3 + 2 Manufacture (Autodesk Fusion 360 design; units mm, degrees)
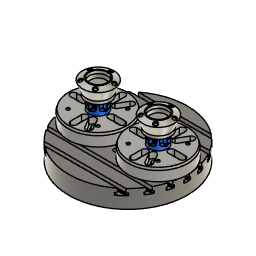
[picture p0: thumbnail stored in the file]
sketch "Sketch1" plane through (0, 0, 0) normal (1, 0, 0) x axis (0, 1, 0)
  line L1 (0, 63.5) -> (0, 0)
  line L2 (42.2596, 63.5) -> (0, 63.5)
  line L3 (66.1278, 54.8127) -> (42.2596, 63.5)
  line L4 (50.8, 12.7) -> (66.1278, 54.8127)
  line L5 (50.8, 0) -> (50.8, 12.7)
  line L6 (0, 0) -> (50.8, 0)
  line L7 (37.6371, 50.8) -> (37.6371, 63.5)
  line L8 (33.0147, 38.1) -> (37.6371, 50.8)
  line L9 (0, 38.1) -> (33.0147, 38.1)
  line L10 (42.2596, 63.5) -> (37.6371, 50.8)
  point P1 (0, 0)
  point P2 (0, 0)
  point P8 (0, 0)
  point P9 (37.6371, 63.5)
  point P12 (0, 38.1)
  point P6 (50.8, 12.7)
  point P7 (50.8, 0)
  point P4 (42.2596, 63.5)
  point P5 (66.1278, 54.8127)
  point P3 (0, 63.5)
  point P10 (37.6371, 50.8)
  coincident P1 P2
  vertical L1
  perpendicular L1 L2
  perpendicular L2 L5
  coincident P1 P8
  horizontal L6
  perpendicular L3 L4
  coincident L2 P9
  perpendicular L2 L7
  coincident L1 P12
  perpendicular L1 L9
  collinear L8 L10
  parallel L4 L10
  dimension "d1" = 101.6
  dimension "d2" distance P6 P7 = 12.7
  dimension "d3" angle L4 L5 = 20
  dimension "d4" distance P4 P5 = 25.4
  dimension "d5" distance P2 P3 = 63.5
  dimension "d7" distance P9 P10 = 12.7
  dimension "d8" distance L2 L9 = 25.4
revolve "Revolve1" sketch "Sketch1" AlongAngle 360 bodies "Part"
work_plane "WorkPlane1" RotateAngle 0
sketch "Sketch2" plane through (0, 54.1937, 59.1563) normal (0, 0.342, 0.9397) x axis (0, 0.9397, -0.342)
  circle C1 centre (0, 0) radius 8.903
  point P1 (0, 0)
  point P2 (0, 0)
  coincident P1 P2
  dimension "d10" diameter C1 = 17.806
copy_paste_bodies "CopyPasteBodies1"
extrude "Extrude1" cut sketch "Sketch2" + "Sketch2" profile of S1:C1 blind -3.175
hole "Hole1" sketch "Sketch2" HoleDepth 12.7 HoleDiameter 10.6426 TipAngle 118
circular_pattern "C-Pattern1" TotalAngle 360
derived_base_feature "Derived Base Feature" bodies "Body1"
base_feature "Base Feature1"
base_feature "Base Feature1" bodies "Body1", "Body2", "Body3", "Body4", "Body5", "Body6"
joint "Assemble2" alignAngle 0 named "d5_2" alignOffsetX 0 named "d6_2" alignOffsetY 0 named "d7_2" alignOffsetZ 0 named "d8_2"
place_component sketch "Sketch2"
sketch "Sketch1" plane through (0, 0, 0) normal (1, 0, 0) x axis (0, 0, -1)
  line L1 (0, 3.1496) -> (0, 0)
  line L2 (-17.1551, 3.1496) -> (0, 3.1496)
  line L3 (-18.9735, 0) -> (-17.1551, 3.1496)
  line L4 (0, 0) -> (-18.9735, 0)
  line L5 (-18.5336, 0) -> (-18.5336, 0.762)
  line L6 (17.1551, 3.1496) -> (0, 3.1496)
  line L7 (18.9735, 0) -> (17.1551, 3.1496)
  line L8 (0, 0) -> (18.9735, 0)
  line L9 (18.5336, 0) -> (18.5336, 0.762)
  line L10 (-44.45, 3.1496) -> (44.45, 3.1496)
  line L11 (-44.45, 34.8996) -> (-44.45, 3.1496)
  line L12 (44.45, 34.8996) -> (-44.45, 34.8996)
  line L13 (44.45, 3.1496) -> (44.45, 34.8996)
  line L14 (-44.45, 34.8996) -> (44.45, 3.1496)
  line L15 (44.45, 34.8996) -> (-44.45, 3.1496)
  circle C1 centre (-19.3548, 1.8796) radius 1.27
  point P1 (0, 0)
  point P2 (0, 0)
  point P6 (0, 0)
  point P8 (-18.5336, 0.762)
  point P9 (-18.5336, 0)
  point P10 (-20.6248, 1.8796)
  point P7 (-19.3548, 1.8796)
  point P3 (0, 3.1496)
  point P11 (0, 3.1496)
  point P4 (-17.1551, 3.1496)
  point P12 (17.1551, 3.1496)
  point P5 (-18.9735, 0)
  point P13 (18.9735, 0)
  point P14 (0, 0)
  point P15 (18.5336, 0.762)
  point P16 (18.5336, 0)
  point P21 (0, 19.0246)
  point P18 (-44.45, 3.1496)
  point P19 (-44.45, 34.8996)
  point P20 (44.45, 34.8996)
  coincident P1 P2
  vertical L1
  perpendicular L1 L2
  coincident P1 P6
  perpendicular L1 L4
  tangent L3 C1
  coincident L3 P8
  coincident L4 P9
  perpendicular L4 L5
  coincident C1 P10
  horizontal P7 P10
  tangent L2 C1
  symmetric P3 L1 P11
  symmetric L1 P4 P12
  symmetric L1 P5 P13
  symmetric L1 P6 P14
  symmetric L1 P8 P15
  symmetric L1 P9 P16
  perpendicular L10 L11
  parallel L10 L12
  parallel L11 L13
  horizontal L10
  coincident L14 P21
  coincident L15 P21
  vertical P3 P21
  coincident P3 L10
  dimension "d1_1" diameter C1 = 2.54
  dimension "d3_1" distance P8 P9 = 0.762
  dimension "d5_1" angle L2 L3 = 60
  dimension "d6_1" distance L1 P10 = 20.6248 (= "( 1.624 / 2 ) * 1 in")
  dimension "d7_1" distance P2 P3 = 3.1496
  dimension "d8_1" distance P18 P19 = 31.75
  dimension "d9_1" distance P19 P20 = 88.9
extrude "Extrude1" new body sketch "Sketch1" profile of L1 L2 L3 L4 L5 L6 L7 L8 L9 L10 L11 L12 L13 distance 50.8 named "d10_1"
sketch "Sketch2" plane through (0, 3.1496, 0) normal (0, -1, 0) x axis (1, 0, 0)
  line L1 (25.4, -44.45) -> (-25.4, -44.45)
  line L2 (25.4, -17.1551) -> (25.4, -44.45)
  line L3 (-25.4, -17.1551) -> (25.4, -17.1551)
  line L4 (-25.4, -44.45) -> (-25.4, -17.1551)
  line L5 (-3.4163, -18.5336) -> (-3.4163, -10.4013)
  line L6 (3.4163, -10.4013) -> (3.4163, -18.5336)
  line L7 (0, -18.5336) -> (0, -10.4013)
  line L8 (25.4, -18.5336) -> (-25.4, -18.5336)
  arc A1 centre (0, -18.5336) radius 3.4163 clockwise from (3.4163, -18.5336) to (-3.4163, -18.5336)
  arc A2 centre (0, -10.4013) radius 3.4163 clockwise from (-3.4163, -10.4013) to (3.4163, -10.4013)
  point P1 (0, 0)
  point P13 (0, -6.985)
  point P11 (0, -18.5336)
  tangent L5 A1
  tangent A1 L6
  parallel L5 L6
  tangent L6 A2
  tangent L5 A2
  perpendicular L3 L7
  coincident P1 L7
  midpoint A2 P13
  coincident P11 L8
  dimension "d12_1" distance P1 P13 = 6.985
  dimension "d13_1" distance L5 L6 = 6.8326
extrude "Extrude2" cut sketch "Sketch2" profile of L3 L5 A1 L6 A2 L8 no distance stored
split "Split1" sketch "Sketch2" bodies "Dovetail"
remove_body "RemoveBody1"
position "Position1"
combine "Combine1" sketch "Sketch2"
joint "Assemble1" alignAngle 0 alignOffsetX 0 alignOffsetY 0 alignOffsetZ 0
remove_instance "RemoveInstance1"
position "Position2"
position "Position3"
component_from_bodies "Body->Comp1"
component_from_bodies "Body->Comp2" sketch "Sketch2"
copy_paste "CopyPaste1"
copy_paste "CopyPaste2"
copy_paste "CopyPaste3"
copy_paste "CopyPaste4"
as_built_joint "As-built1"
ground "Ground1"
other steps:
base_feature "Base Feature1" bodies "Part"
base_feature "Base Feature1" bodies "Stock"
base_feature "Base Feature1" bodies "Stock"
thread "Thread1" sketch "Sketch2" ThreadOffset 0 ThreadDepth 10.0076
create_component "CreateComponent1"
remove_body "RemoveBody2" sketch "Sketch2"
joint_origin "JointOrigin1" sketch "Sketch2"
create_component "CreateComponent1"
create_component "CreateComponent2"
create_component "CreateComponent2"
create_component "CreateComponent3"
create_component "CreateComponent3"
place_component sketch "Sketch2"
remove_body "RemoveBody1"
create_component "CreateComponent4"
place_component sketch "Sketch2"
remove_body "RemoveBody2" sketch "Sketch2"
named bodies: "Part", "Stock", "Dovetail", "Body1", "Body2", "Body3", "Body4", "Body5", "Body6"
